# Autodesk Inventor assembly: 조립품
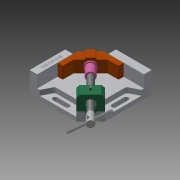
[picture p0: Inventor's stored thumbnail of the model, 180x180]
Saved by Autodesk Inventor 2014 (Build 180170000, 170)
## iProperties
Created: 2019-04
Part Number: 조립품
Document SubType Name: Assembly
Designer: kh
Author: kh
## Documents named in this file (11)
- C:\Users\kh\Desktop\490407V1023\조립품.iam
- C:\Users\kh\Desktop\490407V1023\베이스.ipt
- C:\Users\kh\Desktop\490407V1023\리드스크류.ipt
- C:\Users\kh\Desktop\490407V1023\멈춤나사 M4x5.ipt
- C:\Users\kh\Desktop\490407V1023\멈춤나사 M4x10.ipt
- C:\Users\kh\Desktop\490407V1023\볼트 M4x16.ipt
- C:\Users\kh\Desktop\490407V1023\부시.ipt
- C:\Users\kh\Desktop\490407V1023\서포트.ipt
- C:\Users\kh\Desktop\490407V1023\조.ipt
- C:\Users\kh\Desktop\490407V1023\평행 핀 2.5x24.ipt
- C:\Users\kh\Desktop\490407V1023\핸들.ipt
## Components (1 placed, 1 different names)
1. 핸들:1 — Mate:4
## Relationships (1: Mate 1)
- Mate:4: 핸들:1
